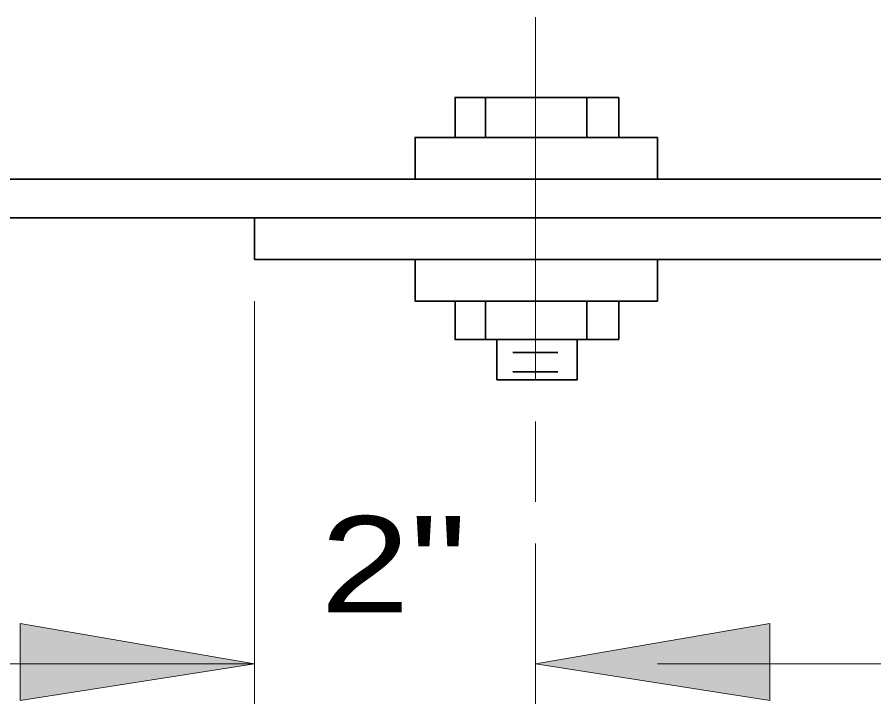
# Model space of a CAD drawing. Extents: x 5332.5 to 5339, y 1824.9 to 1835.1.
# Drawn here: x 5334.112 to 5334.646, y 1826.776 to 1827.204 of the extents above; entities that cross this region are included whole.
import ezdxf

# ---------------------------------------------------------------- set-up
doc = ezdxf.new("R2010")
doc.units = 0
doc.header["$LTSCALE"] = 0.024
for name, color, linetype, lineweight in [('1', 7, 'Continuous', 35), ('10', 7, 'Continuous', 13), ('12', 7, 'Continuous', 53)]:
    doc.layers.add(name, color=color, linetype=linetype, lineweight=lineweight)

msp = doc.modelspace()

# ---------------------------------------------------------------- hatches: boundary and pattern name
at = {"layer": '10'}
for points in [[(5334.114, 1826.778), (5334.114, 1826.826), (5334.26, 1826.801)], [(5334.114, 1826.778), (5334.114, 1826.826), (5334.26, 1826.801)], [(5334.114, 1826.778), (5334.114, 1826.826), (5334.26, 1826.801)], [(5334.114, 1826.778), (5334.114, 1826.826), (5334.26, 1826.801)], [(5334.114, 1826.778), (5334.114, 1826.826), (5334.26, 1826.801)], [(5334.114, 1826.778), (5334.114, 1826.826), (5334.26, 1826.801)], [(5334.114, 1826.778), (5334.114, 1826.826), (5334.26, 1826.801)], [(5334.114, 1826.778), (5334.114, 1826.826), (5334.26, 1826.801)], [(5334.114, 1826.778), (5334.114, 1826.826), (5334.26, 1826.801)], [(5334.114, 1826.778), (5334.114, 1826.826), (5334.26, 1826.801)], [(5334.114, 1826.778), (5334.114, 1826.826), (5334.26, 1826.801)], [(5334.581, 1826.778), (5334.581, 1826.826), (5334.435, 1826.801)], [(5334.581, 1826.778), (5334.581, 1826.826), (5334.435, 1826.801)], [(5334.581, 1826.778), (5334.581, 1826.826), (5334.435, 1826.801)], [(5334.581, 1826.778), (5334.581, 1826.826), (5334.435, 1826.801)], [(5334.581, 1826.778), (5334.581, 1826.826), (5334.435, 1826.801)], [(5334.581, 1826.778), (5334.581, 1826.826), (5334.435, 1826.801)], [(5334.581, 1826.778), (5334.581, 1826.826), (5334.435, 1826.801)], [(5334.581, 1826.778), (5334.581, 1826.826), (5334.435, 1826.801)], [(5334.581, 1826.778), (5334.581, 1826.826), (5334.435, 1826.801)], [(5334.581, 1826.778), (5334.581, 1826.826), (5334.435, 1826.801)], [(5334.581, 1826.778), (5334.581, 1826.826), (5334.435, 1826.801)]]:
    msp.add_hatch(color=256, dxfattribs=at).paths.add_polyline_path(points)

# ---------------------------------------------------------------- linework, layer by layer
at = {"layer": '1'}
for p, q in [((5334.404, 1827.154), (5334.404, 1827.129)), ((5334.404, 1827.154), (5334.404, 1827.129)), ((5334.404, 1827.154), (5334.404, 1827.129)), ((5334.404, 1827.154), (5334.404, 1827.129)), ((5334.404, 1827.154), (5334.404, 1827.129)), ((5334.404, 1827.154), (5334.404, 1827.129)), ((5334.404, 1827.154), (5334.404, 1827.129)), ((5334.404, 1827.154), (5334.404, 1827.129)), ((5334.404, 1827.154), (5334.404, 1827.129)), ((5334.404, 1827.154), (5334.404, 1827.129)), ((5334.404, 1827.154), (5334.404, 1827.129)), ((5334.487, 1827.154), (5334.435, 1827.154)), ((5334.487, 1827.154), (5334.435, 1827.154)), ((5334.487, 1827.154), (5334.435, 1827.154)), ((5334.487, 1827.154), (5334.435, 1827.154)), ((5334.487, 1827.154), (5334.435, 1827.154)), ((5334.487, 1827.154), (5334.435, 1827.154)), ((5334.487, 1827.154), (5334.435, 1827.154)), ((5334.487, 1827.154), (5334.435, 1827.154)), ((5334.487, 1827.154), (5334.435, 1827.154)), ((5334.487, 1827.154), (5334.435, 1827.154)), ((5334.487, 1827.154), (5334.435, 1827.154)), ((5334.467, 1827.154), (5334.467, 1827.129)), ((5334.467, 1827.154), (5334.467, 1827.129)), ((5334.467, 1827.154), (5334.467, 1827.129)), ((5334.467, 1827.154), (5334.467, 1827.129)), ((5334.467, 1827.154), (5334.467, 1827.129)), ((5334.467, 1827.154), (5334.467, 1827.129)), ((5334.467, 1827.154), (5334.467, 1827.129)), ((5334.467, 1827.154), (5334.467, 1827.129)), ((5334.467, 1827.154), (5334.467, 1827.129)), ((5334.467, 1827.154), (5334.467, 1827.129)), ((5334.467, 1827.154), (5334.467, 1827.129)), ((5334.487, 1827.129), (5334.487, 1827.154)), ((5334.487, 1827.129), (5334.487, 1827.154)), ((5334.487, 1827.129), (5334.487, 1827.154)), ((5334.487, 1827.129), (5334.487, 1827.154)), ((5334.487, 1827.129), (5334.487, 1827.154)), ((5334.487, 1827.129), (5334.487, 1827.154)), ((5334.487, 1827.129), (5334.487, 1827.154)), ((5334.487, 1827.129), (5334.487, 1827.154)), ((5334.487, 1827.129), (5334.487, 1827.154)), ((5334.487, 1827.129), (5334.487, 1827.154)), ((5334.487, 1827.129), (5334.487, 1827.154)), ((5334.511, 1827.129), (5334.435, 1827.129)), ((5334.511, 1827.129), (5334.435, 1827.129)), ((5334.511, 1827.129), (5334.435, 1827.129)), ((5334.511, 1827.129), (5334.435, 1827.129)), ((5334.511, 1827.129), (5334.435, 1827.129)), ((5334.511, 1827.129), (5334.435, 1827.129)), ((5334.511, 1827.129), (5334.435, 1827.129)), ((5334.511, 1827.129), (5334.435, 1827.129)), ((5334.511, 1827.129), (5334.435, 1827.129)), ((5334.511, 1827.129), (5334.435, 1827.129)), ((5334.511, 1827.129), (5334.435, 1827.129)), ((5334.511, 1827.103), (5334.511, 1827.129)), ((5334.511, 1827.103), (5334.511, 1827.129)), ((5334.511, 1827.103), (5334.511, 1827.129)), ((5334.511, 1827.103), (5334.511, 1827.129)), ((5334.511, 1827.103), (5334.511, 1827.129)), ((5334.511, 1827.103), (5334.511, 1827.129)), ((5334.511, 1827.103), (5334.511, 1827.129)), ((5334.511, 1827.103), (5334.511, 1827.129)), ((5334.511, 1827.103), (5334.511, 1827.129)), ((5334.511, 1827.103), (5334.511, 1827.129)), ((5334.511, 1827.103), (5334.511, 1827.129)), ((5337.53, 1827.103), (5333.857, 1827.103)), ((5334.26, 1827.079), (5335.492, 1827.079)), ((5334.26, 1827.079), (5335.492, 1827.079)), ((5334.26, 1827.079), (5335.492, 1827.079)), ((5334.26, 1827.079), (5335.492, 1827.079)), ((5334.26, 1827.079), (5335.492, 1827.079)), ((5334.26, 1827.079), (5335.492, 1827.079)), ((5334.26, 1827.079), (5335.492, 1827.079)), ((5334.26, 1827.079), (5335.492, 1827.079)), ((5334.26, 1827.079), (5335.492, 1827.079)), ((5334.26, 1827.079), (5335.492, 1827.079)), ((5334.26, 1827.079), (5335.492, 1827.079)), ((5334.26, 1827.079), (5335.492, 1827.079)), ((5334.26, 1827.079), (5335.492, 1827.079)), ((5334.511, 1827.053), (5334.511, 1827.027)), ((5334.511, 1827.053), (5334.511, 1827.027)), ((5334.511, 1827.053), (5334.511, 1827.027)), ((5334.511, 1827.053), (5334.511, 1827.027)), ((5334.511, 1827.053), (5334.511, 1827.027)), ((5334.511, 1827.053), (5334.511, 1827.027)), ((5334.511, 1827.053), (5334.511, 1827.027)), ((5334.511, 1827.053), (5334.511, 1827.027)), ((5334.511, 1827.053), (5334.511, 1827.027)), ((5334.511, 1827.053), (5334.511, 1827.027)), ((5334.511, 1827.053), (5334.511, 1827.027)), ((5334.404, 1827.003), (5334.404, 1827.027)), ((5334.404, 1827.003), (5334.404, 1827.027)), ((5334.404, 1827.003), (5334.404, 1827.027)), ((5334.404, 1827.003), (5334.404, 1827.027)), ((5334.404, 1827.003), (5334.404, 1827.027)), ((5334.404, 1827.003), (5334.404, 1827.027)), ((5334.404, 1827.003), (5334.404, 1827.027)), ((5334.404, 1827.003), (5334.404, 1827.027)), ((5334.404, 1827.003), (5334.404, 1827.027)), ((5334.404, 1827.003), (5334.404, 1827.027)), ((5334.404, 1827.003), (5334.404, 1827.027)), ((5334.511, 1827.027), (5334.435, 1827.027)), ((5334.511, 1827.027), (5334.435, 1827.027)), ((5334.511, 1827.027), (5334.435, 1827.027)), ((5334.511, 1827.027), (5334.435, 1827.027)), ((5334.511, 1827.027), (5334.435, 1827.027)), ((5334.511, 1827.027), (5334.435, 1827.027)), ((5334.511, 1827.027), (5334.435, 1827.027)), ((5334.511, 1827.027), (5334.435, 1827.027)), ((5334.511, 1827.027), (5334.435, 1827.027)), ((5334.511, 1827.027), (5334.435, 1827.027)), ((5334.511, 1827.027), (5334.435, 1827.027)), ((5334.467, 1827.003), (5334.467, 1827.027)), ((5334.467, 1827.003), (5334.467, 1827.027)), ((5334.467, 1827.003), (5334.467, 1827.027)), ((5334.467, 1827.003), (5334.467, 1827.027)), ((5334.467, 1827.003), (5334.467, 1827.027)), ((5334.467, 1827.003), (5334.467, 1827.027)), ((5334.467, 1827.003), (5334.467, 1827.027)), ((5334.467, 1827.003), (5334.467, 1827.027)), ((5334.467, 1827.003), (5334.467, 1827.027)), ((5334.467, 1827.003), (5334.467, 1827.027)), ((5334.467, 1827.003), (5334.467, 1827.027)), ((5334.487, 1827.027), (5334.487, 1827.003)), ((5334.487, 1827.027), (5334.487, 1827.003)), ((5334.487, 1827.027), (5334.487, 1827.003)), ((5334.487, 1827.027), (5334.487, 1827.003)), ((5334.487, 1827.027), (5334.487, 1827.003)), ((5334.487, 1827.027), (5334.487, 1827.003)), ((5334.487, 1827.027), (5334.487, 1827.003)), ((5334.487, 1827.027), (5334.487, 1827.003)), ((5334.487, 1827.027), (5334.487, 1827.003)), ((5334.487, 1827.027), (5334.487, 1827.003)), ((5334.487, 1827.027), (5334.487, 1827.003)), ((5334.487, 1827.003), (5334.435, 1827.003)), ((5334.487, 1827.003), (5334.435, 1827.003)), ((5334.487, 1827.003), (5334.435, 1827.003)), ((5334.487, 1827.003), (5334.435, 1827.003)), ((5334.487, 1827.003), (5334.435, 1827.003)), ((5334.487, 1827.003), (5334.435, 1827.003)), ((5334.487, 1827.003), (5334.435, 1827.003)), ((5334.487, 1827.003), (5334.435, 1827.003)), ((5334.487, 1827.003), (5334.435, 1827.003)), ((5334.487, 1827.003), (5334.435, 1827.003)), ((5334.487, 1827.003), (5334.435, 1827.003)), ((5334.461, 1827.003), (5334.461, 1826.978)), ((5334.461, 1827.003), (5334.461, 1826.978)), ((5334.461, 1827.003), (5334.461, 1826.978)), ((5334.461, 1827.003), (5334.461, 1826.978)), ((5334.461, 1827.003), (5334.461, 1826.978)), ((5334.461, 1827.003), (5334.461, 1826.978)), ((5334.461, 1827.003), (5334.461, 1826.978)), ((5334.461, 1827.003), (5334.461, 1826.978)), ((5334.461, 1827.003), (5334.461, 1826.978)), ((5334.461, 1827.003), (5334.461, 1826.978)), ((5334.461, 1827.003), (5334.461, 1826.978)), ((5334.421, 1826.995), (5334.449, 1826.995)), ((5334.421, 1826.995), (5334.449, 1826.995)), ((5334.421, 1826.995), (5334.449, 1826.995)), ((5334.421, 1826.995), (5334.449, 1826.995)), ((5334.421, 1826.995), (5334.449, 1826.995)), ((5334.421, 1826.995), (5334.449, 1826.995)), ((5334.421, 1826.995), (5334.449, 1826.995)), ((5334.421, 1826.995), (5334.449, 1826.995)), ((5334.421, 1826.995), (5334.449, 1826.995)), ((5334.421, 1826.995), (5334.449, 1826.995)), ((5334.421, 1826.995), (5334.449, 1826.995)), ((5334.421, 1826.983), (5334.449, 1826.983)), ((5334.421, 1826.983), (5334.449, 1826.983)), ((5334.421, 1826.983), (5334.449, 1826.983)), ((5334.421, 1826.983), (5334.449, 1826.983)), ((5334.421, 1826.983), (5334.449, 1826.983)), ((5334.421, 1826.983), (5334.449, 1826.983)), ((5334.421, 1826.983), (5334.449, 1826.983)), ((5334.421, 1826.983), (5334.449, 1826.983)), ((5334.421, 1826.983), (5334.449, 1826.983)), ((5334.421, 1826.983), (5334.449, 1826.983)), ((5334.421, 1826.983), (5334.449, 1826.983)), ((5334.461, 1826.978), (5334.435, 1826.978)), ((5334.461, 1826.978), (5334.435, 1826.978)), ((5334.461, 1826.978), (5334.435, 1826.978)), ((5334.461, 1826.978), (5334.435, 1826.978)), ((5334.461, 1826.978), (5334.435, 1826.978)), ((5334.461, 1826.978), (5334.435, 1826.978)), ((5334.461, 1826.978), (5334.435, 1826.978)), ((5334.461, 1826.978), (5334.435, 1826.978)), ((5334.461, 1826.978), (5334.435, 1826.978)), ((5334.461, 1826.978), (5334.435, 1826.978)), ((5334.461, 1826.978), (5334.435, 1826.978))]:
    msp.add_line(p, q, dxfattribs=at)
for points in [[(5334.385, 1827.129), (5334.385, 1827.154), (5334.435, 1827.154)], [(5334.385, 1827.129), (5334.385, 1827.154), (5334.435, 1827.154)], [(5334.385, 1827.129), (5334.385, 1827.154), (5334.435, 1827.154)], [(5334.385, 1827.129), (5334.385, 1827.154), (5334.435, 1827.154)], [(5334.385, 1827.129), (5334.385, 1827.154), (5334.435, 1827.154)], [(5334.385, 1827.129), (5334.385, 1827.154), (5334.435, 1827.154)], [(5334.385, 1827.129), (5334.385, 1827.154), (5334.435, 1827.154)], [(5334.385, 1827.129), (5334.385, 1827.154), (5334.435, 1827.154)], [(5334.385, 1827.129), (5334.385, 1827.154), (5334.435, 1827.154)], [(5334.385, 1827.129), (5334.385, 1827.154), (5334.435, 1827.154)], [(5334.385, 1827.129), (5334.385, 1827.154), (5334.435, 1827.154)], [(5334.36, 1827.103), (5334.36, 1827.129), (5334.435, 1827.129)], [(5334.36, 1827.103), (5334.36, 1827.129), (5334.435, 1827.129)], [(5334.36, 1827.103), (5334.36, 1827.129), (5334.435, 1827.129)], [(5334.36, 1827.103), (5334.36, 1827.129), (5334.435, 1827.129)], [(5334.36, 1827.103), (5334.36, 1827.129), (5334.435, 1827.129)], [(5334.36, 1827.103), (5334.36, 1827.129), (5334.435, 1827.129)], [(5334.36, 1827.103), (5334.36, 1827.129), (5334.435, 1827.129)], [(5334.36, 1827.103), (5334.36, 1827.129), (5334.435, 1827.129)], [(5334.36, 1827.103), (5334.36, 1827.129), (5334.435, 1827.129)], [(5334.36, 1827.103), (5334.36, 1827.129), (5334.435, 1827.129)], [(5334.36, 1827.103), (5334.36, 1827.129), (5334.435, 1827.129)], [(5337.53, 1827.103), (5333.857, 1827.103), (5333.857, 1827.079), (5334.26, 1827.079)], [(5337.53, 1827.103), (5333.857, 1827.103), (5333.857, 1827.079), (5334.26, 1827.079)], [(5337.53, 1827.103), (5333.857, 1827.103), (5333.857, 1827.079), (5334.26, 1827.079)], [(5337.53, 1827.103), (5333.857, 1827.103), (5333.857, 1827.079), (5334.26, 1827.079)], [(5337.53, 1827.103), (5333.857, 1827.103), (5333.857, 1827.079), (5334.26, 1827.079)], [(5337.53, 1827.103), (5333.857, 1827.103), (5333.857, 1827.079), (5334.26, 1827.079)], [(5337.53, 1827.103), (5333.857, 1827.103), (5333.857, 1827.079), (5334.26, 1827.079)], [(5337.53, 1827.103), (5333.857, 1827.103), (5333.857, 1827.079), (5334.26, 1827.079)], [(5337.53, 1827.103), (5333.857, 1827.103), (5333.857, 1827.079), (5334.26, 1827.079)], [(5337.53, 1827.103), (5333.857, 1827.103), (5333.857, 1827.079), (5334.26, 1827.079)], [(5337.53, 1827.103), (5333.857, 1827.103), (5333.857, 1827.079), (5334.26, 1827.079)], [(5337.53, 1827.103), (5333.857, 1827.103), (5333.857, 1827.079), (5334.26, 1827.079)], [(5337.53, 1827.103), (5333.857, 1827.103), (5333.857, 1827.079), (5334.26, 1827.079)], [(5334.26, 1827.079), (5334.26, 1827.053), (5335.465, 1827.053)], [(5334.26, 1827.079), (5334.26, 1827.053), (5335.465, 1827.053)], [(5334.26, 1827.079), (5334.26, 1827.053), (5335.465, 1827.053)], [(5334.26, 1827.079), (5334.26, 1827.053), (5335.465, 1827.053)], [(5334.26, 1827.079), (5334.26, 1827.053), (5335.465, 1827.053)], [(5334.26, 1827.079), (5334.26, 1827.053), (5335.465, 1827.053)], [(5334.26, 1827.079), (5334.26, 1827.053), (5335.465, 1827.053)], [(5334.26, 1827.079), (5334.26, 1827.053), (5335.465, 1827.053)], [(5334.26, 1827.079), (5334.26, 1827.053), (5335.465, 1827.053)], [(5334.26, 1827.079), (5334.26, 1827.053), (5335.465, 1827.053)], [(5334.26, 1827.079), (5334.26, 1827.053), (5335.465, 1827.053)], [(5334.26, 1827.079), (5334.26, 1827.053), (5335.465, 1827.053)], [(5334.26, 1827.079), (5334.26, 1827.053), (5335.465, 1827.053)], [(5334.36, 1827.053), (5334.36, 1827.027), (5334.435, 1827.027)], [(5334.36, 1827.053), (5334.36, 1827.027), (5334.435, 1827.027)], [(5334.36, 1827.053), (5334.36, 1827.027), (5334.435, 1827.027)], [(5334.36, 1827.053), (5334.36, 1827.027), (5334.435, 1827.027)], [(5334.36, 1827.053), (5334.36, 1827.027), (5334.435, 1827.027)], [(5334.36, 1827.053), (5334.36, 1827.027), (5334.435, 1827.027)], [(5334.36, 1827.053), (5334.36, 1827.027), (5334.435, 1827.027)], [(5334.36, 1827.053), (5334.36, 1827.027), (5334.435, 1827.027)], [(5334.36, 1827.053), (5334.36, 1827.027), (5334.435, 1827.027)], [(5334.36, 1827.053), (5334.36, 1827.027), (5334.435, 1827.027)], [(5334.36, 1827.053), (5334.36, 1827.027), (5334.435, 1827.027)], [(5334.385, 1827.027), (5334.385, 1827.003), (5334.435, 1827.003)], [(5334.385, 1827.027), (5334.385, 1827.003), (5334.435, 1827.003)], [(5334.385, 1827.027), (5334.385, 1827.003), (5334.435, 1827.003)], [(5334.385, 1827.027), (5334.385, 1827.003), (5334.435, 1827.003)], [(5334.385, 1827.027), (5334.385, 1827.003), (5334.435, 1827.003)], [(5334.385, 1827.027), (5334.385, 1827.003), (5334.435, 1827.003)], [(5334.385, 1827.027), (5334.385, 1827.003), (5334.435, 1827.003)], [(5334.385, 1827.027), (5334.385, 1827.003), (5334.435, 1827.003)], [(5334.385, 1827.027), (5334.385, 1827.003), (5334.435, 1827.003)], [(5334.385, 1827.027), (5334.385, 1827.003), (5334.435, 1827.003)], [(5334.385, 1827.027), (5334.385, 1827.003), (5334.435, 1827.003)], [(5334.411, 1827.003), (5334.411, 1826.978), (5334.435, 1826.978)], [(5334.411, 1827.003), (5334.411, 1826.978), (5334.435, 1826.978)], [(5334.411, 1827.003), (5334.411, 1826.978), (5334.435, 1826.978)], [(5334.411, 1827.003), (5334.411, 1826.978), (5334.435, 1826.978)], [(5334.411, 1827.003), (5334.411, 1826.978), (5334.435, 1826.978)], [(5334.411, 1827.003), (5334.411, 1826.978), (5334.435, 1826.978)], [(5334.411, 1827.003), (5334.411, 1826.978), (5334.435, 1826.978)], [(5334.411, 1827.003), (5334.411, 1826.978), (5334.435, 1826.978)], [(5334.411, 1827.003), (5334.411, 1826.978), (5334.435, 1826.978)], [(5334.411, 1827.003), (5334.411, 1826.978), (5334.435, 1826.978)], [(5334.411, 1827.003), (5334.411, 1826.978), (5334.435, 1826.978)]]:
    msp.add_lwpolyline(points, dxfattribs=at)
at = {"layer": '10'}
for p, q in [((5334.435, 1827.204), (5334.435, 1826.978)), ((5334.435, 1827.204), (5334.435, 1826.978)), ((5334.435, 1827.204), (5334.435, 1826.978)), ((5334.435, 1827.204), (5334.435, 1826.978)), ((5334.435, 1827.204), (5334.435, 1826.978)), ((5334.435, 1827.204), (5334.435, 1826.978)), ((5334.435, 1827.204), (5334.435, 1826.978)), ((5334.435, 1827.204), (5334.435, 1826.978)), ((5334.435, 1827.204), (5334.435, 1826.978)), ((5334.435, 1827.204), (5334.435, 1826.978)), ((5334.435, 1827.204), (5334.435, 1826.978)), ((5334.26, 1827.027), (5334.26, 1826.776)), ((5334.26, 1827.027), (5334.26, 1826.776)), ((5334.26, 1827.027), (5334.26, 1826.776)), ((5334.26, 1827.027), (5334.26, 1826.776)), ((5334.26, 1827.027), (5334.26, 1826.776)), ((5334.26, 1827.027), (5334.26, 1826.776)), ((5334.26, 1827.027), (5334.26, 1826.776)), ((5334.26, 1827.027), (5334.26, 1826.776)), ((5334.26, 1827.027), (5334.26, 1826.776)), ((5334.26, 1827.027), (5334.26, 1826.776)), ((5334.26, 1827.027), (5334.26, 1826.776)), ((5334.435, 1826.952), (5334.435, 1826.902)), ((5334.435, 1826.952), (5334.435, 1826.902)), ((5334.435, 1826.952), (5334.435, 1826.902)), ((5334.435, 1826.952), (5334.435, 1826.902)), ((5334.435, 1826.952), (5334.435, 1826.902)), ((5334.435, 1826.952), (5334.435, 1826.902)), ((5334.435, 1826.952), (5334.435, 1826.902)), ((5334.435, 1826.952), (5334.435, 1826.902)), ((5334.435, 1826.952), (5334.435, 1826.902)), ((5334.435, 1826.952), (5334.435, 1826.902)), ((5334.435, 1826.952), (5334.435, 1826.902)), ((5334.435, 1826.876), (5334.435, 1826.776)), ((5334.435, 1826.876), (5334.435, 1826.776)), ((5334.435, 1826.876), (5334.435, 1826.776)), ((5334.435, 1826.876), (5334.435, 1826.776)), ((5334.435, 1826.876), (5334.435, 1826.776)), ((5334.435, 1826.876), (5334.435, 1826.776)), ((5334.435, 1826.876), (5334.435, 1826.776)), ((5334.435, 1826.876), (5334.435, 1826.776)), ((5334.435, 1826.876), (5334.435, 1826.776)), ((5334.435, 1826.876), (5334.435, 1826.776)), ((5334.435, 1826.876), (5334.435, 1826.776)), ((5333.857, 1826.801), (5334.26, 1826.801)), ((5333.857, 1826.801), (5334.26, 1826.801)), ((5333.857, 1826.801), (5334.26, 1826.801)), ((5333.857, 1826.801), (5334.26, 1826.801)), ((5333.857, 1826.801), (5334.26, 1826.801)), ((5333.857, 1826.801), (5334.26, 1826.801)), ((5333.857, 1826.801), (5334.26, 1826.801)), ((5333.857, 1826.801), (5334.26, 1826.801)), ((5333.857, 1826.801), (5334.26, 1826.801)), ((5333.857, 1826.801), (5334.26, 1826.801)), ((5333.857, 1826.801), (5334.26, 1826.801)), ((5334.895, 1826.801), (5334.511, 1826.801)), ((5334.895, 1826.801), (5334.511, 1826.801)), ((5334.895, 1826.801), (5334.511, 1826.801)), ((5334.895, 1826.801), (5334.511, 1826.801)), ((5334.895, 1826.801), (5334.511, 1826.801)), ((5334.895, 1826.801), (5334.511, 1826.801)), ((5334.895, 1826.801), (5334.511, 1826.801)), ((5334.895, 1826.801), (5334.511, 1826.801)), ((5334.895, 1826.801), (5334.511, 1826.801)), ((5334.895, 1826.801), (5334.511, 1826.801)), ((5334.895, 1826.801), (5334.511, 1826.801))]:
    msp.add_line(p, q, dxfattribs=at)
for points in [[(5334.114, 1826.778), (5334.114, 1826.826), (5334.26, 1826.801)], [(5334.114, 1826.778), (5334.114, 1826.826), (5334.26, 1826.801)], [(5334.114, 1826.778), (5334.114, 1826.826), (5334.26, 1826.801)], [(5334.114, 1826.778), (5334.114, 1826.826), (5334.26, 1826.801)], [(5334.114, 1826.778), (5334.114, 1826.826), (5334.26, 1826.801)], [(5334.114, 1826.778), (5334.114, 1826.826), (5334.26, 1826.801)], [(5334.114, 1826.778), (5334.114, 1826.826), (5334.26, 1826.801)], [(5334.114, 1826.778), (5334.114, 1826.826), (5334.26, 1826.801)], [(5334.114, 1826.778), (5334.114, 1826.826), (5334.26, 1826.801)], [(5334.114, 1826.778), (5334.114, 1826.826), (5334.26, 1826.801)], [(5334.114, 1826.778), (5334.114, 1826.826), (5334.26, 1826.801)], [(5334.581, 1826.778), (5334.581, 1826.826), (5334.435, 1826.801)], [(5334.581, 1826.778), (5334.581, 1826.826), (5334.435, 1826.801)], [(5334.581, 1826.778), (5334.581, 1826.826), (5334.435, 1826.801)], [(5334.581, 1826.778), (5334.581, 1826.826), (5334.435, 1826.801)], [(5334.581, 1826.778), (5334.581, 1826.826), (5334.435, 1826.801)], [(5334.581, 1826.778), (5334.581, 1826.826), (5334.435, 1826.801)], [(5334.581, 1826.778), (5334.581, 1826.826), (5334.435, 1826.801)], [(5334.581, 1826.778), (5334.581, 1826.826), (5334.435, 1826.801)], [(5334.581, 1826.778), (5334.581, 1826.826), (5334.435, 1826.801)], [(5334.581, 1826.778), (5334.581, 1826.826), (5334.435, 1826.801)], [(5334.581, 1826.778), (5334.581, 1826.826), (5334.435, 1826.801)]]:
    msp.add_lwpolyline(points, close=True, dxfattribs=at)

# ---------------------------------------------------------------- texts
at = {"layer": '12', "width": 1.25}
msp.add_text('2"', height=0.06, dxfattribs=at).set_placement((5334.301, 1826.833))

doc.saveas('drawing.dxf')
